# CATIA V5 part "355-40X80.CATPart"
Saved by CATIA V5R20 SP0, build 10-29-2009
Part number: 355-40X80
Definition: NONE
Nomenclature: 355-40X80
Source: Unknown
Description: 355-40X80
Bounding box of the stored display mesh (mm): x -40 to 40, y -26 to 26, z -26 to 26
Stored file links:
  C:\Users\Utente\Desktop\IO LAVORO\3D X SITO CF\X SITO\PLASTICA\355\355-40X80.CATPart
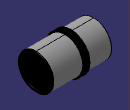
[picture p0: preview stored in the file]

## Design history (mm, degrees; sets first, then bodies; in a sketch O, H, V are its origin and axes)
Body1 "355-40X80" (main body)
  Solid1: solid without history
